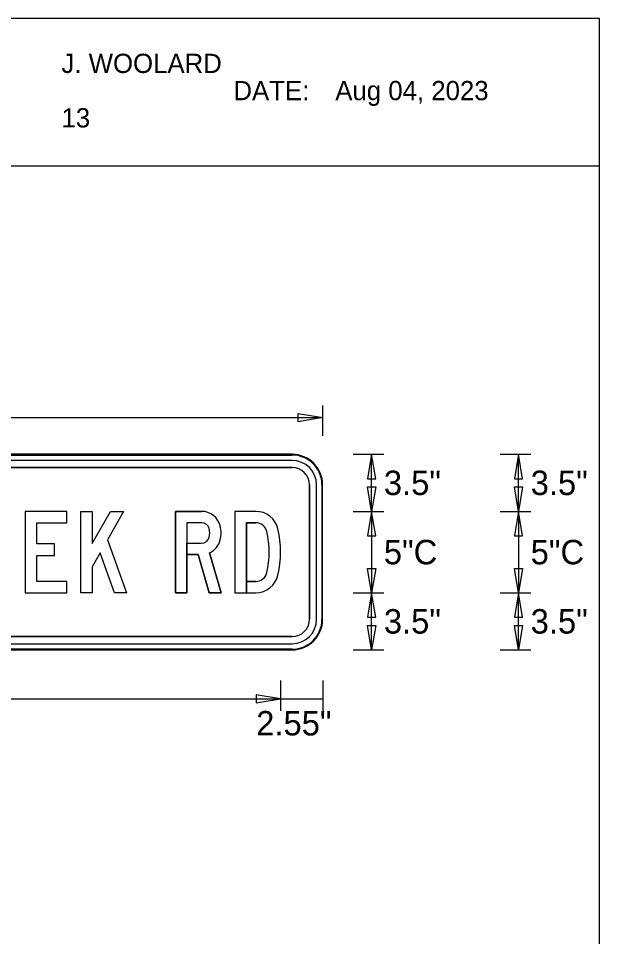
# Model space of a CAD drawing. Extents: x 57.2 to 85.4, y 153.3 to 173.4.
# Drawn here: x 66.748 to 69.717, y 158.039 to 162.735 of the extents above; entities that cross this region are included whole.
import ezdxf

# ---------------------------------------------------------------- set-up
doc = ezdxf.new("R2010")
doc.units = 0
for name, color, linetype in [('Default', 7, 'Continuous'), ('GSBWFILL', 7, 'Continuous'), ('GSCOLORFILL', 7, 'Continuous'), ('GSDIMS', 7, 'Continuous'), ('GSOUTLINE', 7, 'Continuous')]:
    doc.layers.add(name, color=color, linetype=linetype)

msp = doc.modelspace()

# ---------------------------------------------------------------- linework, layer by layer
at = {"layer": 'Default'}
for p, q in [((69.7172, 162.7348), (57.2061, 162.7348)), ((69.7172, 153.3441), (69.7172, 162.7348)), ((63.0203, 161.981), (69.7172, 161.981))]:
    msp.add_line(p, q, dxfattribs=at)
at = {"layer": 'GSBWFILL'}
for p, q in [((68.1463, 160.5057), (64.4588, 160.5057)), ((68.1463, 160.4745), (64.4588, 160.4745)), ((64.4588, 160.438), (68.1463, 160.438)), ((68.2348, 160.3495), (68.2348, 159.6619)), ((68.2713, 159.6619), (68.2713, 160.3495)), ((68.3025, 159.6619), (68.3025, 160.3495)), ((67.6843, 160.0515), (67.6843, 160.0515)), ((67.9607, 159.8557), (67.913, 159.8557)), ((68.1463, 159.5734), (64.4592, 159.5734)), ((64.4588, 159.5057), (68.1463, 159.5057)), ((64.4592, 159.5369), (68.1463, 159.5369))]:
    msp.add_line(p, q, dxfattribs=at)
for points in [[(66.8421, 159.8557), (66.8421, 159.989), (66.9334, 159.989), (66.9334, 160.0474), (66.8421, 160.0474), (66.8421, 160.1557), (66.9963, 160.1557), (66.9963, 160.214), (66.7838, 160.214), (66.7838, 159.7974), (66.9963, 159.7974), (66.9963, 159.8557)], [(67.1654, 160.0012), (67.1254, 159.9307), (67.1254, 159.7974), (67.0671, 159.7974), (67.0671, 160.214), (67.1254, 160.214), (67.1254, 160.0491), (67.2188, 160.214), (67.2859, 160.214), (67.2033, 160.0682), (67.3004, 159.7974), (67.2385, 159.7974)]]:
    msp.add_lwpolyline(points, close=True, dxfattribs=at)
for points in [[(67.6843, 160.1557), (67.6088, 160.1557), (67.6088, 159.7974), (67.5504, 159.7974), (67.5504, 160.214), (67.6843, 160.214)], [(67.9607, 160.214), (67.8546, 160.214), (67.8546, 159.7974), (67.9129, 159.7974), (67.9129, 160.1557), (67.9607, 160.1557)], [(67.7254, 160.0022), (67.7838, 159.7974), (67.7231, 159.7974), (67.6674, 159.9932), (67.6088, 159.9932), (67.6088, 160.0515), (67.6843, 160.0515)], [(67.913, 159.8557), (67.913, 159.7974), (67.9607, 159.7974)]]:
    msp.add_lwpolyline(points, dxfattribs=at)
for centre, radius, start, end in [((68.1463, 160.3495), 0.1562, 0, 90), ((68.1463, 160.3495), 0.125, 0, 90), ((68.1463, 160.3495), 0.0885, 0, 90), ((68.1463, 159.6619), 0.125, 270, 0), ((68.1463, 159.6619), 0.0885, 270, 0), ((68.1463, 159.6619), 0.1562, 270, 0)]:
    msp.add_arc(centre, radius, start, end, dxfattribs=at)
for centre, major_axis, start_param, end_param in [((67.6843, 160.1161), (0, 0.0979), 4.954755, 6.283185), ((67.9607, 160.0974), (0, 0.1167), 4.941184, 6.283185), ((67.6843, 160.1161), (0, 0.0396), 4.954755, 6.283185), ((67.6338, 160.1036), (0, 0.0917), 4.470023, 4.954755), ((67.6338, 160.1036), (0, 0.15), 4.470023, 4.954755), ((67.9607, 160.0974), (0, 0.0583), 4.941184, 6.283185), ((67.5671, 160.0057), (0, 0.5208), 4.483594, 4.941184), ((67.6843, 160.0911), (0, 0.0396), 3.141593, 4.470023), ((67.6843, 160.0911), (0, 0.0979), 3.574819, 4.470023), ((67.5671, 160.0057), (0, 0.4625), 4.483594, 4.941184), ((67.9607, 159.914), (0, 0.0583), 3.141593, 4.483594), ((67.9607, 159.914), (0, 0.1167), 3.141593, 4.483594)]:
    msp.add_ellipse(centre, major_axis=major_axis, ratio=0.999993, start_param=start_param, end_param=end_param, dxfattribs=at)
at = {"layer": 'GSCOLORFILL'}
for p, q in [((68.1463, 160.5057), (64.4588, 160.5057)), ((68.1463, 160.5057), (64.4588, 160.5057)), ((64.4588, 160.5021), (68.1463, 160.5021)), ((68.1463, 160.4745), (64.4588, 160.4745)), ((64.4588, 160.438), (68.1463, 160.438)), ((68.2348, 160.3495), (68.2348, 159.6619)), ((68.2713, 159.6619), (68.2713, 160.3495)), ((68.2989, 160.3495), (68.2989, 159.6619)), ((68.3025, 159.6619), (68.3025, 160.3495)), ((68.3025, 159.6619), (68.3025, 160.3495)), ((67.6843, 160.0515), (67.6843, 160.0515)), ((67.9607, 159.8557), (67.913, 159.8557)), ((68.1463, 159.5734), (64.4592, 159.5734)), ((68.1463, 159.5093), (64.4588, 159.5093)), ((64.4588, 159.5057), (68.1463, 159.5057)), ((64.4588, 159.5057), (68.1463, 159.5057)), ((64.4592, 159.5369), (68.1463, 159.5369))]:
    msp.add_line(p, q, dxfattribs=at)
for points in [[(66.8421, 159.8557), (66.8421, 159.989), (66.9334, 159.989), (66.9334, 160.0474), (66.8421, 160.0474), (66.8421, 160.1557), (66.9963, 160.1557), (66.9963, 160.214), (66.7838, 160.214), (66.7838, 159.7974), (66.9963, 159.7974), (66.9963, 159.8557)], [(67.1654, 160.0012), (67.1254, 159.9307), (67.1254, 159.7974), (67.0671, 159.7974), (67.0671, 160.214), (67.1254, 160.214), (67.1254, 160.0491), (67.2188, 160.214), (67.2859, 160.214), (67.2033, 160.0682), (67.3004, 159.7974), (67.2385, 159.7974)]]:
    msp.add_lwpolyline(points, close=True, dxfattribs=at)
for points in [[(67.6843, 160.1557), (67.6088, 160.1557), (67.6088, 159.7974), (67.5504, 159.7974), (67.5504, 160.214), (67.6843, 160.214)], [(67.9607, 160.214), (67.8546, 160.214), (67.8546, 159.7974), (67.9129, 159.7974), (67.9129, 160.1557), (67.9607, 160.1557)], [(67.7254, 160.0022), (67.7838, 159.7974), (67.7231, 159.7974), (67.6674, 159.9932), (67.6088, 159.9932), (67.6088, 160.0515), (67.6843, 160.0515)], [(67.913, 159.8557), (67.913, 159.7974), (67.9607, 159.7974)]]:
    msp.add_lwpolyline(points, dxfattribs=at)
for centre, radius, start, end in [((68.1463, 160.3495), 0.1562, 0, 90), ((68.1463, 160.3495), 0.1562, 0, 90), ((68.1463, 160.3495), 0.1526, 0, 90), ((68.1463, 160.3495), 0.125, 0, 90), ((68.1463, 160.3495), 0.0885, 0, 90), ((68.1463, 159.6619), 0.1562, 270, 0), ((68.1463, 159.6619), 0.125, 270, 0), ((68.1463, 159.6619), 0.0885, 270, 0), ((68.1463, 159.6619), 0.1562, 270, 0), ((68.1463, 159.6619), 0.1526, 270, 0)]:
    msp.add_arc(centre, radius, start, end, dxfattribs=at)
for centre, major_axis, start_param, end_param in [((67.6843, 160.1161), (0, 0.0979), 4.954755, 6.283185), ((67.9607, 160.0974), (0, 0.1167), 4.941184, 6.283185), ((67.6843, 160.1161), (0, 0.0396), 4.954755, 6.283185), ((67.6338, 160.1036), (0, 0.0917), 4.470023, 4.954755), ((67.6338, 160.1036), (0, 0.15), 4.470023, 4.954755), ((67.9607, 160.0974), (0, 0.0583), 4.941184, 6.283185), ((67.5671, 160.0057), (0, 0.5208), 4.483594, 4.941184), ((67.6843, 160.0911), (0, 0.0396), 3.141593, 4.470023), ((67.6843, 160.0911), (0, 0.0979), 3.574819, 4.470023), ((67.5671, 160.0057), (0, 0.4625), 4.483594, 4.941184), ((67.9607, 159.914), (0, 0.0583), 3.141593, 4.483594), ((67.9607, 159.914), (0, 0.1167), 3.141593, 4.483594)]:
    msp.add_ellipse(centre, major_axis=major_axis, ratio=0.999993, start_param=start_param, end_param=end_param, dxfattribs=at)
at = {"layer": 'GSDIMS'}
for p, q in [((68.3026, 160.5995), (68.3026, 160.7557)), ((64.3025, 160.6932), (68.3026, 160.6932)), ((68.3026, 160.5995), (68.3026, 160.5995)), ((68.4588, 160.5057), (68.6151, 160.5057)), ((68.5526, 160.214), (68.5526, 160.5057)), ((69.2088, 160.5057), (69.3651, 160.5057)), ((69.3026, 160.214), (69.3026, 160.5057)), ((68.4588, 160.214), (68.6151, 160.214)), ((68.4588, 160.214), (68.6151, 160.214)), ((68.5526, 160.214), (68.5526, 159.7974)), ((69.2088, 160.214), (69.3651, 160.214)), ((69.2088, 160.214), (69.3651, 160.214)), ((69.3026, 160.214), (69.3026, 159.7974)), ((68.4588, 159.7974), (68.6151, 159.7974)), ((68.4588, 159.7974), (68.6151, 159.7974)), ((68.5526, 159.5057), (68.5526, 159.7974)), ((69.2088, 159.7974), (69.3651, 159.7974)), ((69.2088, 159.7974), (69.3651, 159.7974)), ((69.3026, 159.5057), (69.3026, 159.7974)), ((68.4588, 159.5057), (68.6151, 159.5057)), ((69.2088, 159.5057), (69.3651, 159.5057)), ((68.088, 159.3494), (68.088, 159.1932)), ((68.088, 159.3494), (68.088, 159.1932)), ((68.3026, 159.3494), (68.3026, 159.1932)), ((68.3026, 159.3494), (68.3026, 159.1932)), ((64.5171, 159.2557), (68.088, 159.2557)), ((68.088, 159.2557), (68.3026, 159.2557))]:
    msp.add_line(p, q, dxfattribs=at)
for points in [[(68.3026, 160.6932), (68.1776, 160.6724), (68.1776, 160.7141)], [(68.5526, 160.5057), (68.5317, 160.3807), (68.5734, 160.3807)], [(69.3026, 160.5057), (69.2817, 160.3807), (69.3234, 160.3807)], [(68.5526, 160.214), (68.5317, 160.339), (68.5734, 160.339)], [(69.3026, 160.214), (69.2817, 160.339), (69.3234, 160.339)], [(68.5526, 160.214), (68.5317, 160.089), (68.5734, 160.089)], [(69.3026, 160.214), (69.2817, 160.089), (69.3234, 160.089)], [(68.5526, 159.7974), (68.5317, 159.9224), (68.5734, 159.9224)], [(69.3026, 159.7974), (69.2817, 159.9224), (69.3234, 159.9224)], [(68.5526, 159.7974), (68.5317, 159.6724), (68.5734, 159.6724)], [(69.3026, 159.7974), (69.2817, 159.6724), (69.3234, 159.6724)], [(68.5526, 159.5057), (68.5317, 159.6307), (68.5734, 159.6307)], [(69.3026, 159.5057), (69.2817, 159.6307), (69.3234, 159.6307)], [(68.088, 159.2557), (67.963, 159.2765), (67.963, 159.2348)]]:
    msp.add_lwpolyline(points, close=True, dxfattribs=at)
at = {"layer": 'GSOUTLINE'}
for p, q in [((68.1463, 160.5057), (64.4588, 160.5057)), ((68.1463, 160.4745), (64.4588, 160.4745)), ((68.1463, 160.438), (64.4588, 160.438)), ((68.2348, 159.6619), (68.2348, 160.3495)), ((68.2713, 159.6619), (68.2713, 160.3495)), ((68.3025, 159.6619), (68.3025, 160.3495)), ((67.6843, 160.214), (67.5504, 160.214)), ((67.6843, 160.1557), (67.6843, 160.1557)), ((67.9129, 159.8557), (67.9607, 159.8557)), ((67.9607, 159.7974), (67.9607, 159.7974)), ((64.4588, 159.5734), (68.1463, 159.5734)), ((64.4588, 159.5369), (68.1463, 159.5369)), ((64.4588, 159.5057), (68.1463, 159.5057))]:
    msp.add_line(p, q, dxfattribs=at)
for points in [[(66.8421, 159.8557), (66.8421, 159.989), (66.9334, 159.989), (66.9334, 160.0474), (66.8421, 160.0474), (66.8421, 160.1557), (66.9963, 160.1557), (66.9963, 160.214), (66.7838, 160.214), (66.7838, 159.7974), (66.9963, 159.7974), (66.9963, 159.8557)], [(67.1654, 160.0012), (67.1254, 159.9307), (67.1254, 159.7974), (67.0671, 159.7974), (67.0671, 160.214), (67.1254, 160.214), (67.1254, 160.0491), (67.2188, 160.214), (67.2859, 160.214), (67.2033, 160.0682), (67.3004, 159.7974), (67.2385, 159.7974)]]:
    msp.add_lwpolyline(points, close=True, dxfattribs=at)
for points in [[(67.5504, 160.214), (67.5504, 159.7974), (67.6088, 159.7974), (67.6088, 159.9932), (67.6674, 159.9932), (67.7231, 159.7974), (67.7838, 159.7974), (67.7254, 160.0022)], [(67.9607, 160.214), (67.8546, 160.214), (67.8546, 159.7974), (67.9607, 159.7974)], [(67.6843, 160.1557), (67.6088, 160.1557), (67.6088, 160.0515), (67.6843, 160.0515)], [(67.9607, 160.1557), (67.9129, 160.1557), (67.9129, 159.8557)]]:
    msp.add_lwpolyline(points, dxfattribs=at)
for centre, radius, start, end in [((68.1463, 160.3495), 0.1562, 0, 90), ((68.1463, 160.3495), 0.125, 0, 90), ((68.1463, 160.3495), 0.0885, 0, 90), ((68.1463, 159.6619), 0.125, 270, 0), ((68.1463, 159.6619), 0.0885, 270, 0), ((68.1463, 159.6619), 0.1562, 270, 0)]:
    msp.add_arc(centre, radius, start, end, dxfattribs=at)
for centre, major_axis, start_param, end_param in [((67.6843, 160.1161), (0, 0.0979), 4.954755, 6.283185), ((67.9607, 160.0974), (0, 0.1167), 4.941184, 6.283185), ((67.6843, 160.1161), (0, 0.0396), 4.954755, 6.283185), ((67.6338, 160.1036), (0, 0.0917), 4.470023, 4.954755), ((67.6338, 160.1036), (0, 0.15), 4.470023, 4.954755), ((67.9607, 160.0974), (0, 0.0583), 4.941184, 6.283185), ((67.5671, 160.0057), (0, 0.5208), 4.483594, 4.941184), ((67.6843, 160.0911), (0, 0.0396), 3.141593, 4.470023), ((67.6843, 160.0911), (0, 0.0979), 3.574819, 4.470023), ((67.5671, 160.0057), (0, 0.4625), 4.483594, 4.941184), ((67.9607, 159.914), (0, 0.0583), 3.141593, 4.483594), ((67.9607, 159.914), (0, 0.1167), 3.141593, 4.483594)]:
    msp.add_ellipse(centre, major_axis=major_axis, ratio=0.999993, start_param=start_param, end_param=end_param, dxfattribs=at)

# ---------------------------------------------------------------- texts
at = {"layer": 'Default'}
for s, height, p in [('J. WOOLARD', 0.09843, (66.9685, 162.4555)), ('DATE:', 0.09843, (67.8468, 162.3164)), ('Aug 04, 2023', 0.098425, (68.367, 162.3164)), ('13', 0.09843, (66.9685, 162.1772))]:
    msp.add_text(s, height=height, dxfattribs=at).set_placement(p)
at = {"layer": 'GSDIMS'}
for s, p in [('3.5"', (68.6151, 160.2974)), ('3.5"', (69.3651, 160.2974)), ('5"C', (68.6151, 159.9432)), ('5"C', (69.3651, 159.9432)), ('3.5"', (68.6151, 159.589)), ('3.5"', (69.3651, 159.589)), ('2.55"', (67.9631, 159.0682))]:
    msp.add_text(s, height=0.125, dxfattribs=at).set_placement(p)

doc.saveas('drawing.dxf')
